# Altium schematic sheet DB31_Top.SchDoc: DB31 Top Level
size A4; Organization: Altium Limited.; Address1: Level 3, 12a Rodborough Rd; Address2: Frenchs Forest 2086; Address3: NSW; Address4: AUSTRALIA; SheetNumber: 2; SheetTotal: 21
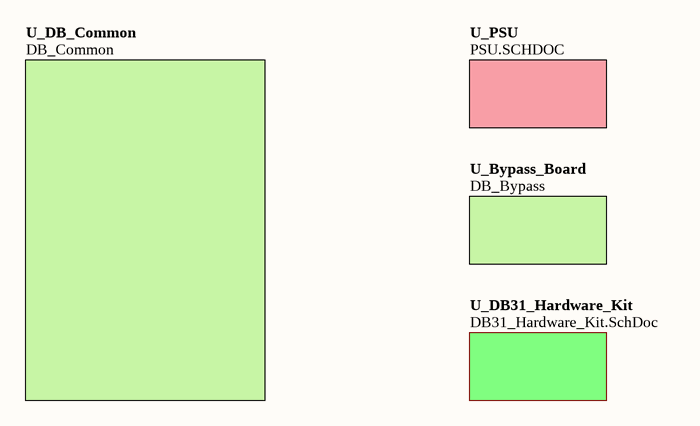
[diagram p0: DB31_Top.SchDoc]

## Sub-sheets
U_Bypass_Board = DB_Bypass: no entries
U_DB31_Hardware_Kit = DB31_Hardware_Kit.SchDoc: no entries
U_DB_Common = DB_Common: no entries
U_PSU = PSU.SCHDOC: no entries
